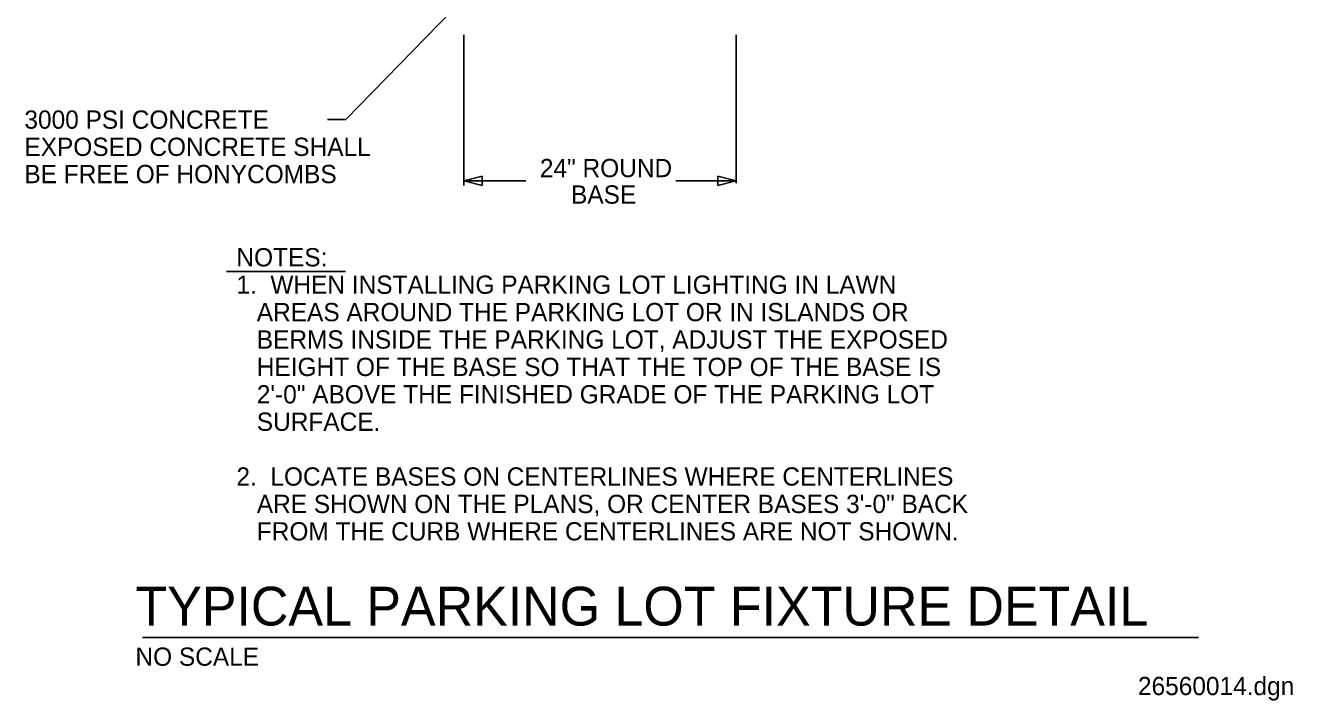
# Model space of a CAD drawing. Extents: x 10117 to 10169, y 10050 to 10161.
# Drawn here: x 10122.92 to 10169.15, y 10050.24 to 10074.88 of the extents above; entities that cross this region are included whole.
import ezdxf

# ---------------------------------------------------------------- set-up
doc = ezdxf.new("R2010")
doc.units = 0
doc.layers.add('G-ANNO-TEXT', color=7, linetype='Continuous')

msp = doc.modelspace()

# ---------------------------------------------------------------- linework, layer by layer
at = {"layer": 'G-ANNO-TEXT'}
for p, q in [((10134.607, 10071.442), (10139.256, 10076.212)), ((10138.915, 10074.54), (10138.915, 10069.042)), ((10148.851, 10074.54), (10148.851, 10069.123)), ((10133.94, 10071.442), (10134.607, 10071.442)), ((10138.915, 10069.204), (10141.172, 10069.204)), ((10146.648, 10069.204), (10148.851, 10069.204)), ((10130.261, 10065.9), (10134.602, 10065.9)), ((10127.195, 10052.545), (10165.72, 10052.545))]:
    msp.add_line(p, q, dxfattribs=at)
for points in [[(10139.582, 10069.038), (10138.915, 10069.204), (10139.582, 10069.371)], [(10148.184, 10069.371), (10148.851, 10069.204), (10148.184, 10069.038)]]:
    msp.add_lwpolyline(points, close=True, dxfattribs=at)

# ---------------------------------------------------------------- texts
for s, height, p in [('3000 PSI CONCRETE', 0.66667, (10122.885, 10071.108)), ('EXPOSED CONCRETE SHALL', 0.66667, (10122.885, 10070.115)), ('24" ROUND', 0.6667, (10141.691, 10069.34)), ('BE FREE OF HONYCOMBS', 0.66667, (10122.885, 10069.121)), ('BASE', 0.6667, (10142.827, 10068.374)), ('NOTES:', 0.6667, (10130.62, 10066.084)), ('1.  WHEN INSTALLING PARKING LOT LIGHTING IN LAWN', 0.66667, (10130.62, 10065.084)), ('   AREAS AROUND THE PARKING LOT OR IN ISLANDS OR', 0.66667, (10130.62, 10064.084)), ('   BERMS INSIDE THE PARKING LOT, ADJUST THE EXPOSED', 0.66667, (10130.62, 10063.084)), ('   HEIGHT OF THE BASE SO THAT THE TOP OF THE BASE IS', 0.66667, (10130.62, 10062.084)), ('   2\'-0" ABOVE THE FINISHED GRADE OF THE PARKING LOT', 0.66667, (10130.62, 10061.084)), ('   SURFACE.', 0.66667, (10130.62, 10060.084)), ('2.  LOCATE BASES ON CENTERLINES WHERE CENTERLINES', 0.66667, (10130.62, 10058.084)), ('   ARE SHOWN ON THE PLANS, OR CENTER BASES 3\'-0" BACK ', 0.66667, (10130.62, 10057.084)), ('   FROM THE CURB WHERE CENTERLINES ARE NOT SHOWN.', 0.66667, (10130.62, 10056.084)), ('TYPICAL PARKING LOT FIXTURE DETAIL', 1.41667, (10126.937, 10052.978)), ('NO SCALE', 0.6667, (10126.937, 10051.51)), ('26560014.dgn', 0.66667, (10163.51, 10050.439))]:
    msp.add_text(s, height=height, dxfattribs=at).set_placement(p)

doc.saveas('drawing.dxf')
